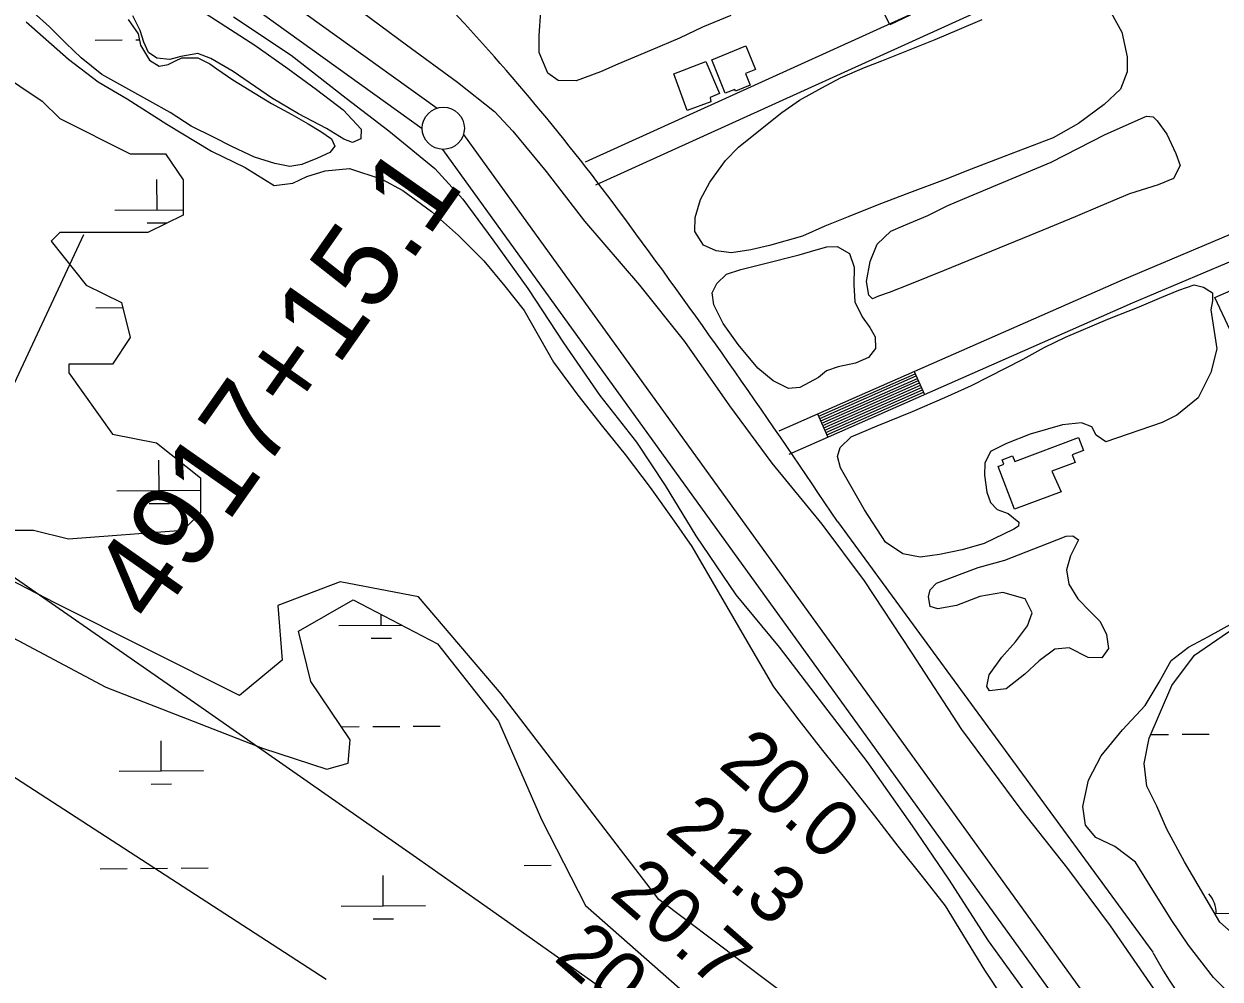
# Model space of a CAD drawing. Extents: x 3540316 to 3578335, y 553172 to 578787.
# Drawn here: x 3550058 to 3551474, y 566083 to 567214 of the extents above; entities that cross this region are included whole.
import ezdxf

# ---------------------------------------------------------------- set-up
doc = ezdxf.new("R2010")
doc.units = 0
for name, color, linetype in [('V-BLDG-OTLN', 7, 'Continuous'), ('V-LEVE-TOET', 7, 'Continuous'), ('V-RIVR-RANG', 7, 'Continuous'), ('V-ROAD-CNTR', 7, 'Continuous'), ('V-SITE-VEGE', 7, 'Continuous'), ('V-SURV-IDEN', 7, 'Continuous'), ('V-SURV-LINE', 7, 'Continuous'), ('V-TOPO-MINR', 7, 'Continuous'), ('V-WETL-SWMP', 7, 'Continuous')]:
    doc.layers.add(name, color=color, linetype=linetype)

msp = doc.modelspace()

# ---------------------------------------------------------------- linework, layer by layer
at = {"layer": 'V-BLDG-OTLN'}
for points in [[(3551088.6, 567262.9), (3551107.3, 567224.3), (3551082.9, 567212.5), (3551062.7, 567254.4)], [(3550888.3, 567131.9), (3550872.3, 567171.4), (3550912.8, 567187.7), (3550924.1, 567159.8), (3550912.2, 567155), (3550917.7, 567141.3), (3550900.3, 567134.2), (3550899.6, 567136)], [(3550865.3, 567169.4), (3550881.6, 567131.5), (3550870.3, 567126.6), (3550871.1, 567121.5), (3550843.4, 567111.3), (3550827.3, 567154.6)], [(3551467.5, 566889.7), (3551508.9, 566908), (3551529.7, 566861), (3551518.2, 566855.9), (3551523.2, 566844.5), (3551494.7, 566831.9)], [(3551285.6, 566659.9), (3551230.4, 566639.1), (3551211.3, 566689.9), (3551218, 566692.4), (3551215.9, 566697.8), (3551228.3, 566702.5), (3551231, 566695.5), (3551306.5, 566723.9), (3551312.3, 566708.5), (3551298.8, 566703.4), (3551302.2, 566694.5), (3551274.6, 566684.1)]]:
    msp.add_lwpolyline(points, close=True, dxfattribs=at)
at = {"layer": 'V-LEVE-TOET'}
for points in [[(3550306.5, 567222), (3550374.6, 567176.6), (3550439.6, 567125.8), (3550490, 567087.3), (3550544.8, 567042.6), (3550577.6, 567006.4), (3550613.2, 566958.1), (3550654.7, 566900.4), (3550696.7, 566836.1), (3550739.8, 566773.7), (3550783.3, 566718.7), (3550817.3, 566667.2), (3550853.4, 566607.6), (3550900.9, 566537.8), (3550951.9, 566475.8), (3551009.6, 566400.6), (3551055.9, 566340.6), (3551109.3, 566264.2), (3551152.4, 566201), (3551199.6, 566128.1), (3551242.7, 566068)], [(3550459.3, 567227.3), (3550510.9, 567188.9), (3550571.6, 567145), (3550615.3, 567110.1), (3550637, 567086.7), (3550676.5, 567039.2), (3550721.6, 566980.3), (3550786.8, 566904.4), (3550840.1, 566837.8), (3550893.5, 566761.7), (3550943.4, 566693.5), (3551002.6, 566621.4), (3551052.5, 566554.4), (3551108.3, 566469.8), (3551167.7, 566378.5), (3551238.1, 566283.8), (3551293.4, 566213.6), (3551343.7, 566145.8), (3551399.1, 566065.9)]]:
    msp.add_lwpolyline(points, dxfattribs=at)
at = {"layer": 'V-RIVR-RANG'}
msp.add_line((3550128.8, 566964), (3549356, 565316.2), dxfattribs=at)
at = {"layer": 'V-ROAD-CNTR'}
for p, q in [((3551112, 566802.4), (3551124.1, 566774.9)), ((3550997.6, 566752), (3551009.7, 566724.5))]:
    msp.add_line(p, q, dxfattribs=at)
for points in [[(3550722.8, 567050.5), (3551263.6, 567296.5)], [(3550735.2, 567023.2), (3551276, 567269.2)], [(3550951.9, 566731.8), (3551358.3, 566910.9), (3551524.6, 566981.2)], [(3550964, 566704.3), (3551370.2, 566883.4), (3551538.4, 566954.5)], [(3550998.9, 566749.2), (3551113.2, 566799.6)], [(3551000.1, 566746.5), (3551114.4, 566796.9)], [(3551001.3, 566743.7), (3551115.7, 566794.1)], [(3551002.5, 566741), (3551116.9, 566791.4)], [(3551003.7, 566738.2), (3551118.1, 566788.7)], [(3551004.9, 566735.5), (3551119.3, 566785.9)], [(3551006.1, 566732.7), (3551120.5, 566783.2)], [(3551007.3, 566730), (3551121.7, 566780.4)], [(3551008.5, 566727.3), (3551122.9, 566777.7)], [(3551021, 566624.5), (3551394.3, 566114.5)]]:
    msp.add_lwpolyline(points, dxfattribs=at)
for centre, radius, start, end in [((3548558.5, 565360.5), 2742.5, 36.0967, 43.195), ((3543896.3, 561895.1), 8551.5, 33.57602, 36.45407), ((3551752.1, 566303.1), 404.5, 207.7944, 264.9308)]:
    msp.add_arc(centre, radius, start, end, dxfattribs=at)
at = {"layer": 'V-SITE-VEGE'}
for points in [[(3550256.4, 567237.2), (3550331.8, 567188.7), (3550370.7, 567161), (3550404.7, 567136.3), (3550436.2, 567112), (3550457.5, 567089.1), (3550457.1, 567077.8), (3550447.3, 567073.3), (3550437, 567077.2), (3550416.3, 567089.8), (3550383.3, 567107.2), (3550351.3, 567126.1), (3550306, 567157.6), (3550279.4, 567172.7), (3550264.2, 567178.9), (3550244.1, 567175.3), (3550230.9, 567171.8), (3550215.7, 567173.2), (3550205.8, 567180), (3550200.4, 567192.2), (3550195.9, 567205.9), (3550187.4, 567223.5)], [(3550895, 567223.7), (3550861.4, 567209.8), (3550834, 567197), (3550800.8, 567182.7), (3550761.3, 567166), (3550740.6, 567157.2), (3550712, 567146.4), (3550690.5, 567146.6), (3550678.2, 567155.6), (3550667.9, 567179.8), (3550668.1, 567199.8), (3550669.9, 567228.8)], [(3551344.8, 567226.9), (3551357.7, 567203.9), (3551363.8, 567175), (3551363.9, 567156.9), (3551356.2, 567136.7), (3551336.7, 567118.5), (3551306.5, 567095.7), (3551276.2, 567078.8), (3551218.5, 567056.8), (3551179.3, 567041.8), (3551148.5, 567029.4), (3551106.4, 567013.9), (3551070.2, 566999.9), (3551033.6, 566985.4), (3551006.2, 566974.4), (3550979.8, 566962.5), (3550940.6, 566951.4), (3550918.6, 566946.4), (3550895.6, 566942.8), (3550877.4, 566945.1), (3550862.6, 566951.9), (3550852.2, 566968), (3550852.6, 566984.6), (3550858.8, 567005.8), (3550870, 567026.4), (3550888.4, 567052.1), (3550904, 567067.9), (3550927.9, 567087.2), (3550955.2, 567108.9), (3550976.2, 567123.3), (3551002.6, 567138.2), (3551024.6, 567150.1), (3551052.9, 567162.1), (3551073.5, 567170.1), (3551136.6, 567195.5), (3551165.4, 567207.5), (3551192.3, 567219)], [(3550061.2, 567216.1), (3550111.2, 567172), (3550146.2, 567145.2), (3550180.6, 567125.2), (3550227.6, 567095.1), (3550280.4, 567063.1), (3550320.1, 567043.6), (3550354.5, 567022.6), (3550376.7, 567025.2), (3550393.1, 567033), (3550414.8, 567040), (3550443.7, 567042.6), (3550481.9, 567029.8), (3550506.6, 567016.5), (3550540.6, 566991.6), (3550572.6, 566963.3), (3550602.7, 566933.2), (3550627.6, 566903.4), (3550650.4, 566874.6), (3550685.1, 566813.1), (3550713.9, 566774.2), (3550743.1, 566737.2), (3550769.9, 566704.1), (3550799.6, 566664.7), (3550827.8, 566624.9), (3550848.8, 566595.1), (3550921.1, 566470.6), (3550945.5, 566428.8), (3550975.2, 566389.4), (3551003.5, 566353.4), (3551032.7, 566317), (3551064.8, 566276.2), (3551092.6, 566240.1), (3551121.3, 566204.2), (3551148.6, 566169.6), (3551194.9, 566093.2), (3551216.9, 566060.5)], [(3551004.6, 566030.4), (3550809.5, 566176.9), (3550623.1, 566420.5), (3550525.3, 566535.4), (3550432.7, 566553.2), (3550359, 566525), (3550364.1, 566460.4), (3550313.5, 566418.4), (3550095.6, 566527.9), (3549655.2, 566755.9)], [(3551415.8, 566459.9), (3551436.3, 566475.7), (3551460.3, 566488.6), (3551490.1, 566505)], [(3551491.7, 566058.7), (3551466, 566084.6), (3551436.3, 566123.1), (3551416, 566153.4), (3551389.2, 566196.3), (3551373.8, 566221.2), (3551349.2, 566239.7), (3551327, 566250.3), (3551314.7, 566265), (3551311.6, 566287), (3551318.2, 566318.4), (3551333.2, 566347), (3551358.5, 566378.1), (3551385.3, 566406.7), (3551401.8, 566434.3), (3551415.8, 566459.9)]]:
    msp.add_lwpolyline(points, dxfattribs=at)
for points in [[(3551069.8, 566891.3), (3551062.5, 566888.3), (3551058.1, 566892.7), (3551055.6, 566908.7), (3551059.8, 566932.6), (3551067.9, 566953), (3551084.3, 566968.2), (3551098.9, 566974.6), (3551128, 566987), (3551151.7, 566998.8), (3551169.6, 567006.3), (3551273.8, 567050.2), (3551337.8, 567082.8), (3551386.7, 567104.5), (3551394.5, 567103.6), (3551399.4, 567099.2), (3551410.7, 567083.3), (3551421.6, 567060.5), (3551426.5, 567046), (3551418.9, 567030.8), (3551400.4, 567023.4), (3551366.5, 567012.5), (3551332.1, 566998.1), (3551302.5, 566985.3), (3551264.2, 566969.5), (3551240, 566959.6), (3551147.4, 566922), (3551106.2, 566905.2), (3551082.4, 566895.8)], [(3550998.5, 566795.1), (3550976.7, 566783.2), (3550963.1, 566782.2), (3550945.1, 566791.3), (3550927, 566806.2), (3550903.4, 566834.3), (3550885.8, 566858.9), (3550874.9, 566881.2), (3550872.9, 566895.3), (3550878.2, 566906.5), (3550889.7, 566917.3), (3550906.7, 566922.8), (3550933.4, 566929.7), (3550975.6, 566940.2), (3550996, 566946.2), (3551008.6, 566949.7), (3551020.8, 566950.3), (3551035.4, 566942.1), (3551040.9, 566925.6), (3551040.5, 566904.7), (3551041.6, 566884.8), (3551050.5, 566866.9), (3551059.4, 566854.3), (3551065.8, 566843.2), (3551065.9, 566829.5), (3551057.7, 566818.8), (3551042.6, 566811.9), (3551021.8, 566807.8), (3551008.2, 566802.9)], [(3551229.9, 566615.5), (3551194.7, 566598.6), (3551168.7, 566591.1), (3551141.8, 566585.5), (3551118.8, 566582.4), (3551098.6, 566586.2), (3551077.9, 566600.2), (3551053.1, 566638.3), (3551024.8, 566688.1), (3551021.3, 566701.4), (3551024.2, 566712.2), (3551037.3, 566725), (3551068.1, 566738), (3551109.7, 566754.9), (3551148.3, 566771.4), (3551179.6, 566785.8), (3551240.7, 566816.7), (3551265.6, 566830.6), (3551291, 566843), (3551340.9, 566864), (3551378.1, 566878.9), (3551405, 566890.4), (3551425, 566898.4), (3551443.1, 566904.9), (3551454.4, 566902), (3551464.8, 566895.2), (3551464.8, 566885.9), (3551463, 566875.1), (3551470.1, 566829.1), (3551463, 566801), (3551448, 566771), (3551422.6, 566750.7), (3551405.5, 566741.8), (3551338.5, 566718.8), (3551327.2, 566727), (3551322.2, 566736.8), (3551309.9, 566741.6), (3551287.4, 566739), (3551249.2, 566728), (3551221.3, 566717), (3551202.2, 566707.5), (3551195.5, 566693.7), (3551195.1, 566679.5), (3551197.7, 566659.4), (3551202.2, 566647.2), (3551210.1, 566638.9), (3551222.9, 566634.1), (3551235.7, 566623.9), (3551235.2, 566619)], [(3551138.1, 566551.6), (3551187.5, 566570.1), (3551219.3, 566578.7), (3551269.7, 566598.6), (3551291.7, 566607.1), (3551299.5, 566607.7), (3551306.4, 566602.8), (3551296.8, 566584.1), (3551292, 566567.4), (3551295, 566550.3), (3551305.5, 566533.2), (3551320.3, 566518.1), (3551332.1, 566506.4), (3551339.6, 566490.7), (3551341.7, 566474.1), (3551333.9, 566463.2), (3551317.7, 566463.6), (3551295.1, 566475.2), (3551278.4, 566473.6), (3551259.9, 566459.8), (3551242.8, 566444), (3551220.9, 566426.6), (3551200.8, 566424), (3551197.8, 566429.4), (3551200.6, 566443.2), (3551215.7, 566463.9), (3551231.8, 566482.1), (3551245.9, 566500.9), (3551251.6, 566516.6), (3551243.2, 566533.2), (3551216.6, 566540.4), (3551189.7, 566535.8), (3551161.8, 566525.3), (3551139.8, 566521.2), (3551130.9, 566524.1), (3551128.9, 566535.4), (3551130.8, 566543.7)]]:
    msp.add_lwpolyline(points, close=True, dxfattribs=at)
at = {"layer": 'V-SURV-LINE'}
for points in [[(3550069.8, 567457.4), (3550547.2, 567114.1)], [(3550529.6, 567089.7), (3550052.3, 567433.1)], [(3550578.5, 567082.8), (3551472.8, 565843.5)], [(3551448.5, 565825.9), (3550554.2, 567065.2)]]:
    msp.add_lwpolyline(points, dxfattribs=at)
msp.add_circle((3550554.6, 567090.2), 25, dxfattribs=at)
at = {"layer": 'V-TOPO-MINR'}
for points in [[(3550744.9, 566069.6), (3550610.3, 566164.7), (3550522.9, 566226.2), (3550435.5, 566287.6), (3550347.9, 566348.8), (3550260.2, 566409.9), (3549714.6, 566789)], [(3550416.1, 566082.3), (3549598.6, 566611.9)]]:
    msp.add_lwpolyline(points, dxfattribs=at)
at = {"layer": 'V-WETL-SWMP'}
for p, q in [((3550142.7, 567194.7), (3550174.7, 567194.9)), ((3550190.7, 567195), (3550195, 567195.1)), ((3550017.7, 567163.8), (3550080.1, 567122.4)), ((3550080.1, 567122.4), (3550100.9, 567101.6)), ((3550100.9, 567101.6), (3550184.2, 567060.1)), ((3550184.2, 567060.1), (3550225.8, 567060.1)), ((3550225.8, 567060.1), (3550246.6, 567029)), ((3550215.9, 566993.6), (3550215.6, 567029.5)), ((3550246.6, 567029), (3550246.6, 566987.5)), ((3550165.9, 566993.2), (3550246.6, 566993.8)), ((3550204, 566978.1), (3550228, 566978.3)), ((3550246.6, 566987.5), (3550204.9, 566966.8)), ((3550100.9, 566966.7), (3550090.5, 566956.4)), ((3550204.9, 566966.8), (3550100.9, 566966.7)), ((3550090.5, 566956.4), (3550132.1, 566904.5)), ((3550132.1, 566904.5), (3550173.7, 566883.8)), ((3550173.7, 566883.8), (3550184.1, 566842.3)), ((3550143.4, 566877.7), (3550175.2, 566878)), ((3550184.1, 566842.3), (3550163.3, 566811.1)), ((3550163.3, 566811.1), (3550111.3, 566811.1)), ((3550111.3, 566811.1), (3550111.3, 566800.8)), ((3550111.3, 566800.8), (3550163.3, 566728.2)), ((3550163.3, 566728.2), (3550215.3, 566717.8)), ((3550215.3, 566717.8), (3550267.3, 566676.3)), ((3550218.4, 566661.4), (3550218.1, 566697.3)), ((3550267.3, 566676.3), (3550267.3, 566634.8)), ((3550168.4, 566661), (3550267.3, 566661.8)), ((3550206.5, 566645.9), (3550230.5, 566646.1)), ((3550267.3, 566634.8), (3550246.5, 566614)), ((3550069.6, 566614), (3550028, 566614)), ((3550111.2, 566603.7), (3550069.6, 566614)), ((3550246.5, 566614), (3550111.2, 566603.7)), ((3549953.5, 566535.5), (3550155.2, 566428.6)), ((3550383.4, 566494.7), (3550447.9, 566532)), ((3550447.9, 566532), (3550547.6, 566479.7)), ((3550481.1, 566501.8), (3550481, 566514.7)), ((3550431.1, 566501.4), (3550505.2, 566502)), ((3550397.7, 566435), (3550383.4, 566494.7)), ((3550469.2, 566486.3), (3550493.2, 566486.5)), ((3550547.6, 566479.7), (3550619.8, 566388.1)), ((3550155.2, 566428.6), (3550340.5, 566356.2)), ((3550444.4, 566366.2), (3550397.7, 566435)), ((3550619.8, 566388.1), (3550671.4, 566271)), ((3550434, 566381.5), (3550455.1, 566381.7)), ((3550471.1, 566381.8), (3550503.1, 566382)), ((3550519.1, 566382.2), (3550551.1, 566382.4)), ((3551391.9, 566372.4), (3551412.9, 566372.6)), ((3551428.9, 566372.7), (3551460.9, 566373)), ((3550220.9, 566329.2), (3550220.7, 566365.1)), ((3550340.5, 566356.2), (3550416.9, 566331.4)), ((3550442.2, 566338.5), (3550444.4, 566366.2)), ((3550170.9, 566328.8), (3550270.9, 566329.6)), ((3550416.9, 566331.4), (3550442.2, 566338.5)), ((3550209, 566313.7), (3550233, 566313.9)), ((3550671.4, 566271), (3550722.9, 566170)), ((3550148.4, 566213.4), (3550180.4, 566213.6)), ((3550196.4, 566213.7), (3550228.4, 566214)), ((3550244.4, 566214.1), (3550276.4, 566214.4)), ((3550650.3, 566217.2), (3550682.3, 566217.5)), ((3550698.3, 566217.6), (3550698.6, 566217.6)), ((3550483.6, 566169.6), (3550483.3, 566205.5)), ((3550433.6, 566169.2), (3550533.6, 566170)), ((3550722.9, 566170), (3550834.4, 566071.7)), ((3551467.5, 566160.4), (3551539.4, 566161)), ((3550471.7, 566154.1), (3550495.7, 566154.3))]:
    msp.add_line(p, q, dxfattribs=at)
for points in [[(3550181.6, 567219.2), (3550193.4, 567202.2), (3550196.5, 567188.5), (3550206.9, 567170.9), (3550218.2, 567163.6), (3550229, 567165.7), (3550237.8, 567170.1), (3550245.1, 567173.6), (3550264.2, 567173.7), (3550278.5, 567166.5), (3550286.8, 567160.7), (3550305.5, 567147.6), (3550351.3, 567119.5), (3550375.4, 567106.4), (3550394.6, 567095.3), (3550409.9, 567086.5), (3550422.2, 567077.8), (3550426.1, 567069), (3550420.3, 567061.6), (3550405.7, 567054.7), (3550387.1, 567047.2), (3550372.9, 567045.1), (3550355.2, 567048.4), (3550331.2, 567056.1), (3550305.1, 567068.2), (3550282.5, 567079.8), (3550256.4, 567092.8), (3550231.3, 567108.8), (3550207.2, 567122.4), (3550150.7, 567153.8), (3550126, 567173.8), (3550107.8, 567190.8), (3550088.5, 567210.2), (3550069.3, 567227.8)], [(3551554.1, 566054.6), (3551527.2, 566096.4), (3551497.4, 566129.2), (3551473.5, 566150.1), (3551431.8, 566221.7), (3551410.9, 566260.5), (3551398.9, 566287.4), (3551387, 566311.2), (3551384, 566338.1), (3551390, 566367.9), (3551416.8, 566430.6), (3551443.7, 566466.4), (3551482.5, 566493.2), (3551506.3, 566508.1), (3551539.2, 566529), (3551575, 566546.9), (3551631.7, 566552.9), (3551658.5, 566543.9), (3551685.4, 566514.1), (3551706.2, 566493.2), (3551748, 566406.7), (3551840.5, 566188.9)]]:
    msp.add_lwpolyline(points, dxfattribs=at)
msp.add_arc((3551434.1, 566160.6), 35.2, 359.6699, 41.2135, dxfattribs=at)

# ---------------------------------------------------------------- texts
at = {"layer": 'V-RIVR-RANG'}
for s, p in [('20.0', (3550878.6, 566334.6)), ('21.3', (3550815.2, 566257.3)), ('20.7', (3550749.5, 566181.8)), ('20.7', (3550683.9, 566106.3))]:
    msp.add_text(s, height=67, rotation=318.8483, dxfattribs=at).set_placement(p)
at = {"layer": 'V-SURV-IDEN'}
msp.add_text('4917+15.1', height=100, rotation=54.9311, dxfattribs=at).set_placement((3550213.6, 566499.9))

doc.saveas('drawing.dxf')
